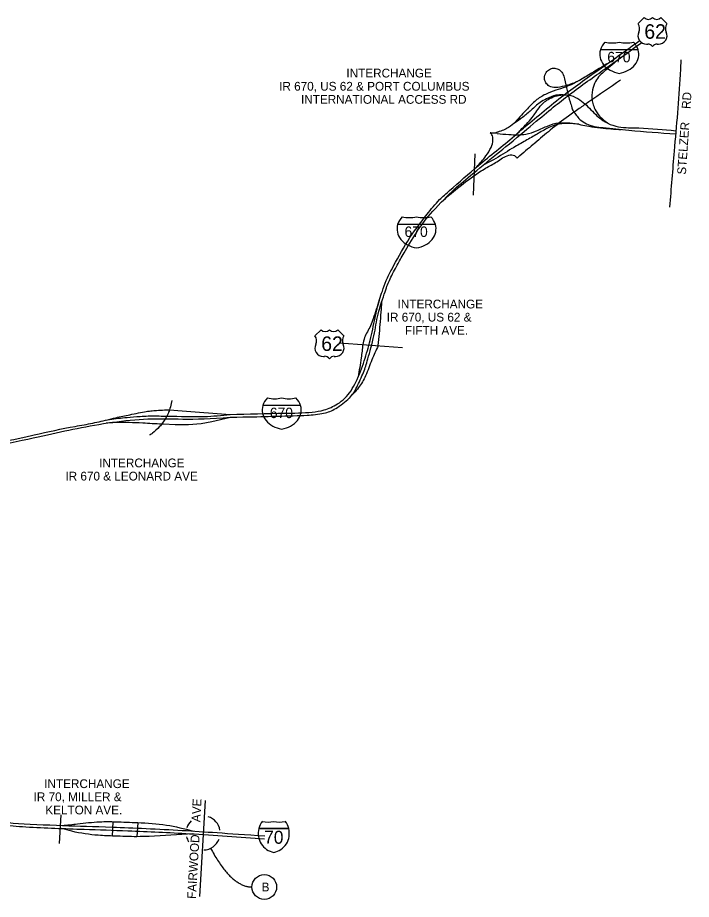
# Model space of a CAD drawing. Extents: x -13 to 322, y -402 to 112.
# Drawn here: x 6.02 to 14.81, y 98.15 to 109.64 of the extents above; entities that cross this region are included whole.
import ezdxf

# ---------------------------------------------------------------- set-up
doc = ezdxf.new("R2010")
doc.units = 0
for name, color, linetype in [('GM_X_Interstate_Shield', 7, 'Continuous'), ('GM_X_US_Shield', 7, 'Continuous'), ('SC_Scratch1', 7, 'Continuous'), ('SH_Data', 7, 'Continuous'), ('SH_Text', 7, 'Continuous')]:
    doc.layers.add(name, color=color, linetype=linetype)

msp = doc.modelspace()

# ---------------------------------------------------------------- linework, layer by layer
at = {"layer": 'GM_X_Interstate_Shield'}
for p, q in [((14.112, 109.225), (13.62, 109.225)), ((14.112, 109.225), (13.62, 109.225)), ((11.468, 106.948), (10.977, 106.948)), ((11.468, 106.948), (10.977, 106.948)), ((9.71, 104.585), (9.219, 104.585)), ((9.71, 104.585), (9.219, 104.585)), ((9.165, 99.068), (9.557, 99.068)), ((9.557, 99.068), (9.165, 99.068)), ((9.557, 99.068), (9.165, 99.068))]:
    msp.add_line(p, q, dxfattribs=at)
for centre, start, end in [((9.412, 99.006), 141.669, 165.8066), ((9.287, 99.406), 253.0091, 286.9909), ((9.435, 99.406), 253.0091, 286.9909), ((9.31, 99.006), 14.1934, 38.331), ((9.412, 99.006), 165.8066, 258.463), ((9.31, 99.006), 281.537, 14.1934)]:
    msp.add_arc(centre, 0.254, start, end, dxfattribs=at)
for centre, start_param, end_param in [((13.929, 109.167), 2.47259, 2.911027), ((13.773, 109.568), 4.415841, 5.008937), ((13.959, 109.568), 4.415841, 5.008937), ((13.802, 109.167), 0.230566, 0.669003), ((13.929, 109.167), 2.911027, 4.511031), ((13.802, 109.167), 4.913747, 6.513751), ((11.286, 106.89), 2.911027, 4.511031), ((11.286, 106.89), 2.47259, 2.911027), ((11.129, 107.291), 4.415841, 5.008937), ((11.315, 107.291), 4.415841, 5.008937), ((11.159, 106.89), 4.913747, 6.513751), ((11.159, 106.89), 0.230566, 0.669003), ((9.528, 104.527), 2.47259, 2.911027), ((9.372, 104.928), 4.415841, 5.008937), ((9.557, 104.928), 4.415841, 5.008937), ((9.401, 104.527), 0.230566, 0.669003), ((9.528, 104.527), 2.911027, 4.511031), ((9.401, 104.527), 4.913747, 6.513751)]:
    msp.add_ellipse(centre, major_axis=(0.318, 0), ratio=0.8, start_param=start_param, end_param=end_param, dxfattribs=at)
at = {"layer": 'GM_X_US_Shield'}
for p, q in [((14.189, 109.644), (14.111, 109.566)), ((14.488, 109.566), (14.41, 109.644)), ((14.221, 109.298), (14.237, 109.298)), ((14.362, 109.298), (14.378, 109.298)), ((9.977, 105.573), (9.898, 105.495)), ((10.276, 105.495), (10.197, 105.573)), ((10.008, 105.227), (10.024, 105.227)), ((10.15, 105.227), (10.165, 105.227))]:
    msp.add_line(p, q, dxfattribs=at)
for centre, radius, start, end in [((14.244, 109.7), 0.0786, 225.573, 314.427), ((14.355, 109.7), 0.0786, 225.573, 314.427), ((14.021, 109.502), 0.11, 334.5471, 35.0009), ((14.578, 109.502), 0.11, 144.9991, 205.4529), ((14.22, 109.408), 0.11, 154.8319, 270.6383), ((14.379, 109.408), 0.11, 269.3617, 25.1681), ((14.237, 109.22), 0.0786, 36.8699, 90), ((14.362, 109.22), 0.0786, 90, 143.1301), ((10.032, 105.629), 0.0786, 225.573, 314.427), ((10.142, 105.629), 0.0786, 225.573, 314.427), ((9.808, 105.432), 0.11, 334.5471, 35.0009), ((10.366, 105.432), 0.11, 144.9991, 205.4529), ((10.007, 105.337), 0.11, 154.8319, 270.6383), ((10.167, 105.337), 0.11, 269.3617, 25.1681), ((10.024, 105.149), 0.0786, 36.8699, 90), ((10.15, 105.149), 0.0786, 90, 143.1301)]:
    msp.add_arc(centre, radius, start, end, dxfattribs=at)
at = {"layer": 'SC_Scratch1'}
msp.add_line((6.582, 99.249), (6.562, 98.874), dxfattribs=at)
at = {"layer": 'SH_Data'}
for p, q in [((12.272, 108.132), (12.181, 108.143)), ((11.982, 107.869), (11.963, 107.327)), ((10.218, 105.405), (11.038, 105.344)), ((8.001, 104.528), (8.166, 104.517)), ((8.166, 104.517), (8.792, 104.47)), ((8.553, 104.376), (8.795, 104.433)), ((7.901, 104.346), (7.924, 104.346)), ((7.924, 104.346), (8.074, 104.338)), ((8.074, 104.338), (8.249, 104.34)), ((8.249, 104.34), (8.412, 104.352)), ((8.412, 104.352), (8.553, 104.376)), ((8.465, 99.436), (8.391, 98.182)), ((7.263, 99.159), (7.254, 98.972)), ((7.263, 99.159), (7.254, 98.972)), ((7.587, 99.147), (7.577, 98.963)), ((7.587, 99.147), (7.577, 98.963))]:
    msp.add_line(p, q, dxfattribs=at)
msp.add_circle((9.237, 98.307), 0.161, dxfattribs=at)
for start, end in [(134.8432, 162.4068), (9.5298, 72.6505), (192.8172, 211.1657), (272.2221, 338.8979)]:
    msp.add_arc((8.44, 99.012), 0.222, start, end, dxfattribs=at)
for points in [[(12.635, 108.219), (13.144, 108.635), (13.633, 108.988), (14.134, 109.347)], [(13.888, 109.125), (13.702, 108.969), (13.569, 108.833), (13.525, 108.735), (13.51, 108.597), (13.521, 108.525), (13.548, 108.452), (13.61, 108.359), (13.727, 108.262)], [(13.705, 109.04), (13.435, 108.878), (13.311, 108.809), (13.15, 108.751), (13.033, 108.734), (12.953, 108.752), (12.91, 108.794), (12.891, 108.853), (12.913, 108.928), (12.956, 108.969), (13.01, 108.985), (13.068, 108.973), (13.127, 108.918), (13.153, 108.844), (13.225, 108.545), (13.249, 108.47), (13.271, 108.418), (13.287, 108.397), (13.325, 108.346), (13.395, 108.285), (13.483, 108.241), (13.541, 108.225), (13.655, 108.21), (13.991, 108.176), (14.601, 108.128)], [(14.67, 109.096), (14.66, 108.901), (14.582, 107.903), (14.522, 107.173)], [(13.452, 108.887), (13.163, 108.738), (13.04, 108.697), (12.904, 108.644), (12.778, 108.563), (12.67, 108.457), (12.591, 108.371), (12.422, 108.212), (12.284, 108.151)], [(13.883, 108.827), (13.468, 108.545), (13.343, 108.459), (13.203, 108.36), (12.967, 108.178), (12.766, 108.007)], [(13.133, 108.637), (13.041, 108.631), (12.916, 108.585), (12.833, 108.537), (12.718, 108.439), (12.605, 108.343), (12.499, 108.268)], [(12.54, 108.136), (12.655, 108.257), (12.731, 108.343), (12.777, 108.407), (12.836, 108.488), (12.892, 108.545), (12.956, 108.588), (13.057, 108.625), (13.122, 108.636), (13.234, 108.628), (13.353, 108.571), (13.515, 108.423), (13.596, 108.347), (13.716, 108.267), (13.855, 108.222), (14.121, 108.205), (14.604, 108.169)], [(8.792, 104.47), (9.502, 104.486), (9.863, 104.501), (10.018, 104.528), (10.191, 104.606), (10.288, 104.681), (10.431, 104.891), (10.541, 105.169), (10.617, 105.435), (10.682, 105.728), (10.739, 105.968), (10.777, 106.079), (10.827, 106.216), (10.899, 106.36), (11.108, 106.73), (11.36, 107.08), (11.524, 107.271), (11.653, 107.389), (12.03, 107.716), (12.498, 108.101), (12.635, 108.219)], [(12.272, 108.132), (12.428, 108.12), (12.649, 108.125), (12.788, 108.167), (12.939, 108.235), (13.075, 108.273), (13.12, 108.274), (13.257, 108.27), (13.367, 108.248), (13.468, 108.228), (13.622, 108.206), (13.893, 108.185)], [(13.34, 108.254), (13.152, 108.264), (13.016, 108.239), (12.923, 108.198), (12.777, 108.115), (12.624, 108.027), (12.466, 107.937)], [(12.007, 107.697), (12.128, 107.84), (12.194, 107.952), (12.219, 108.052), (12.205, 108.117), (12.181, 108.143)], [(12.29, 108.153), (12.2, 108.138), (12.181, 108.143)], [(12.768, 108.009), (12.571, 107.844), (12.535, 107.813)], [(11.55, 107.243), (11.971, 107.583), (12.122, 107.68), (12.271, 107.765), (12.426, 107.85), (12.499, 107.846), (12.525, 107.823), (12.535, 107.813)], [(12.466, 107.937), (12.226, 107.792), (12.09, 107.72)], [(10.736, 105.957), (10.657, 105.716), (10.621, 105.624), (10.546, 105.471), (10.522, 105.382)], [(10.722, 105.367), (10.738, 105.523), (10.765, 105.844), (10.774, 105.957)], [(10.724, 105.367), (10.64, 105.181), (10.558, 104.973), (10.466, 104.819), (10.342, 104.682)], [(10.522, 105.382), (10.5, 105.207), (10.461, 104.958)], [(8.031, 104.653), (8.029, 104.635), (8.006, 104.545), (7.983, 104.482), (7.923, 104.377), (7.868, 104.306), (7.778, 104.225), (7.742, 104.199)], [(7.178, 104.396), (7.301, 104.427), (7.483, 104.465), (7.596, 104.49), (7.699, 104.509), (7.757, 104.516), (7.833, 104.523), (7.938, 104.528), (8.001, 104.528)], [(5.737, 104.097), (6.203, 104.195), (6.237, 104.203), (6.772, 104.314), (7.001, 104.357), (7.22, 104.404), (7.447, 104.431), (7.617, 104.444), (7.724, 104.45), (7.95, 104.448), (7.98, 104.448), (8.454, 104.442), (8.792, 104.47)], [(7.177, 104.36), (7.351, 104.368), (7.474, 104.368), (7.652, 104.36), (7.901, 104.346)], [(3.035, 99.2), (3.527, 99.26), (3.83, 99.276), (4.065, 99.283), (4.578, 99.264), (4.968, 99.23), (5.794, 99.119), (6.128, 99.092), (6.888, 99.06), (7.459, 99.04), (8.263, 99.002), (9.242, 98.936)], [(6.603, 99.11), (6.801, 99.13), (7.092, 99.158), (7.299, 99.158), (7.587, 99.147), (7.96, 99.115), (8.31, 99.037)], [(8.306, 98.999), (7.735, 98.967), (7.577, 98.963), (7.283, 98.971), (7.073, 98.981), (6.729, 99.034), (6.593, 99.072)]]:
    msp.add_spline(points, degree=3, dxfattribs=at)
for points, degree in [([(12.659, 108.19), (12.902, 108.389), (13.138, 108.591), (13.647, 108.952), (13.902, 109.135), (14.156, 109.317)], 3), ([(8.793, 104.433), (9.039, 104.438), (9.286, 104.443), (9.655, 104.455), (9.774, 104.453), (10.034, 104.482), (10.154, 104.53), (10.37, 104.688), (10.437, 104.807), (10.542, 105.037), (10.578, 105.157), (10.679, 105.515), (10.707, 105.763), (10.825, 106.106), (10.864, 106.22), (10.982, 106.436), (11.039, 106.545), (11.227, 106.858), (11.374, 107.061), (11.705, 107.405), (11.902, 107.562), (12.278, 107.877), (12.472, 108.029), (12.66, 108.191)], 3), ([(5.744, 104.06), (6.248, 104.167), (6.76, 104.292), (7.751, 104.454), (8.282, 104.39), (8.795, 104.433)], 3), ([(5.004, 99.263), (5.125, 99.249), (5.246, 99.233), (5.623, 99.179), (5.876, 99.141), (6.653, 99.105), (7.172, 99.094), (8.21, 99.048), (8.727, 99.008), (9.245, 98.973)], 3), ([(8.537, 98.813), (8.807, 98.307), (9.076, 98.307)], 2)]:
    msp.add_open_spline(points, degree=degree, dxfattribs=at)

# ---------------------------------------------------------------- texts
at = {"layer": 'GM_X_Interstate_Shield'}
for s, height, p in [('670', 0.1356, (13.71, 109.062)), ('670', 0.1356, (11.066, 106.785)), ('670', 0.1356, (9.309, 104.422)), ('70', 0.1695, (9.235, 98.871))]:
    msp.add_text(s, height=height, dxfattribs=at).set_placement(p)
at = {"layer": 'GM_X_US_Shield'}
for p in [(14.193, 109.369), (9.98, 105.298)]:
    msp.add_text('62', height=0.1888, dxfattribs=at).set_placement(p)
at = {"layer": 'SH_Data'}
msp.add_text('B', height=0.114, dxfattribs=at).set_placement((9.203, 98.25))
at = {"layer": 'SH_Text'}
for s, height, p in [('INTERCHANGE', 0.11437, (10.308, 108.864)), ('IR 670, US 62 & PORT COLUMBUS', 0.11437, (9.431, 108.692)), ('INTERNATIONAL ACCESS RD', 0.11437, (9.716, 108.521)), ('INTERCHANGE', 0.11437, (10.976, 105.852)), ('IR 670, US 62 &', 0.11437, (10.834, 105.681)), ('FIFTH AVE.', 0.1144, (11.071, 105.509)), ('INTERCHANGE', 0.11437, (7.084, 103.78)), ('IR 670 & LEONARD AVE', 0.11437, (6.644, 103.608)), ('INTERCHANGE', 0.11437, (6.368, 99.597)), ('IR 70, MILLER &', 0.11437, (6.229, 99.426)), ('KELTON AVE.', 0.11437, (6.382, 99.254))]:
    msp.add_text(s, height=height, dxfattribs=at).set_placement(p)
for s, height, rotation, p in [('STELZER    RD', 0.11437, 86.0247, (14.734, 107.594)), ('AVE', 0.1144, 86.6267, (8.401, 99.151)), ('FAIRWOOD', 0.1144, 86.6267, (8.345, 98.149))]:
    msp.add_text(s, height=height, rotation=rotation, dxfattribs=at).set_placement(p)

doc.saveas('drawing.dxf')
